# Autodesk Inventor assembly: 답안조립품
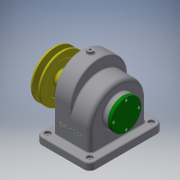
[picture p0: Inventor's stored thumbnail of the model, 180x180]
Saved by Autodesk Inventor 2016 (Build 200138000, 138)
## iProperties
Created: 2017-11
Part Number: 답안조립품
Material: 일반
Document SubType Name: Assembly
Designer: 605-06
Author: 605-06
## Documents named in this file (14)
- C:\Users\605-06\Desktop\471107V1017\답안조립품.iam
- C:\Users\605-06\Desktop\471107V1017\V-벨트풀리.ipt
- C:\Users\605-06\Desktop\471107V1017\뒤커버.ipt
- C:\Users\605-06\Desktop\471107V1017\멈춤나사 - M4 x 10.ipt
- 멈춤나사 - M4 x 10.ipt
- C:\Users\605-06\Desktop\471107V1017\베어링 6002.ipt
- C:\Users\605-06\Desktop\471107V1017\본체.ipt
- C:\Users\605-06\Desktop\471107V1017\볼트 M3 x 8.ipt
- C:\Users\605-06\Desktop\471107V1017\스퍼기어.ipt
- C:\Users\605-06\Desktop\471107V1017\앞커버.ipt
- C:\Users\605-06\Desktop\471107V1017\오일 실 15 30 7.ipt
- C:\Users\605-06\Desktop\471107V1017\축.ipt
- C:\Users\605-06\Desktop\471107V1017\키 - 5 x 5 x 18.ipt
- C:\Users\605-06\Desktop\471107V1017\키 - 6 x 6 x 22.ipt
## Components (1 placed, 1 different names)
1. V-벨트풀리:1 — 각도:1
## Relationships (1: Angle 1)
- 각도:1 [Angle]: V-벨트풀리:1
